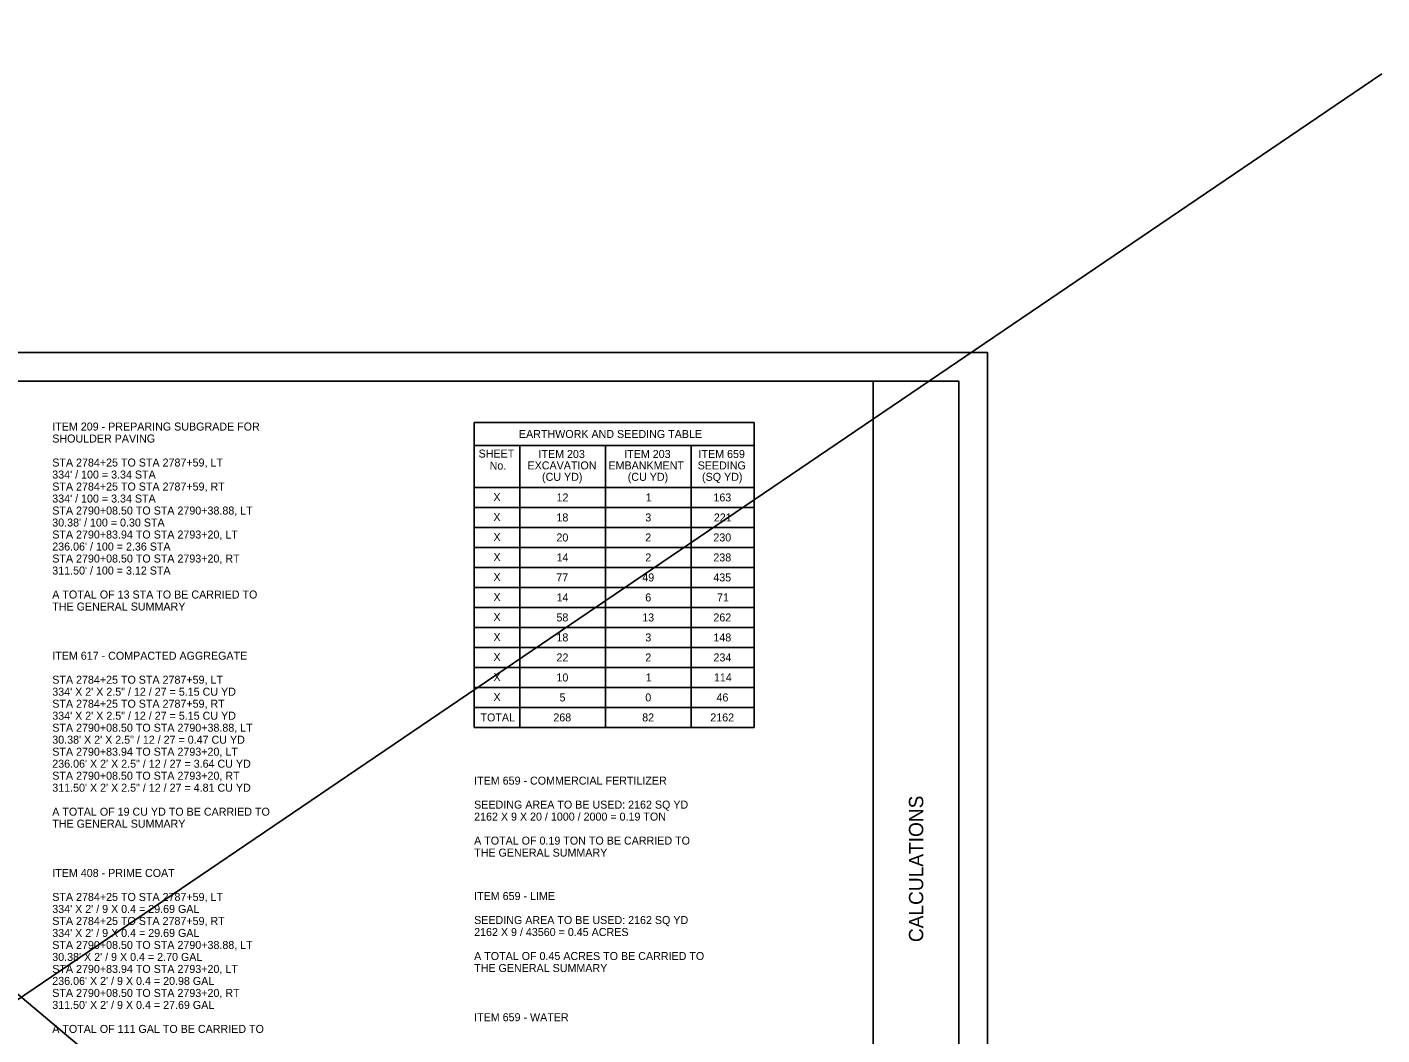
# Model space of a CAD drawing. Extents: x 0 to 126, y 0 to 48.
# Drawn here: x 101.92 to 125.62, y 30.04 to 47.67 of the extents above; entities that cross this region are included whole.
import ezdxf

# ---------------------------------------------------------------- set-up
doc = ezdxf.new("R2010")
doc.units = 0
for name, color, linetype in [('SH_Border', 7, 'Continuous'), ('SH_Cut_Line', 7, 'Continuous'), ('SH_Data', 7, 'Continuous'), ('SH_Text', 7, 'Continuous'), ('TX_P_1', 7, 'Continuous')]:
    doc.layers.add(name, color=color, linetype=linetype)

msp = doc.modelspace()

# ---------------------------------------------------------------- linework, layer by layer
at = {"layer": 'SH_Border'}
msp.add_line((116.721, 20.477), (116.721, 41.477), dxfattribs=at)
msp.add_lwpolyline([(86.221, 41.477), (118.221, 41.477), (118.221, 20.477), (86.221, 20.477)], close=True, dxfattribs=at)
at = {"layer": 'SH_Cut_Line'}
msp.add_lwpolyline([(84.721, 19.977), (118.721, 19.977), (118.721, 41.977), (84.721, 41.977)], close=True, dxfattribs=at)
at = {"layer": 'SH_Text'}
for p, q in [((81.554, 47.674), (123.873, 12.206)), ((125.622, 46.858), (82.136, 17.34))]:
    msp.add_line(p, q, dxfattribs=at)
at = {"layer": 'TX_P_1'}
for p, q in [((114.638, 40.753), (109.738, 40.753)), ((109.738, 40.753), (109.738, 35.417)), ((114.638, 40.753), (114.638, 35.417)), ((114.638, 40.353), (109.738, 40.353)), ((110.538, 40.353), (110.538, 35.417)), ((112.038, 40.353), (112.038, 35.417)), ((113.538, 40.353), (113.538, 35.417)), ((114.638, 39.617), (109.738, 39.617)), ((114.638, 39.267), (109.738, 39.267)), ((114.638, 38.917), (109.738, 38.917)), ((114.638, 38.567), (109.738, 38.567)), ((114.638, 38.217), (109.738, 38.217)), ((114.638, 37.867), (109.738, 37.867)), ((114.638, 37.517), (109.738, 37.517)), ((114.638, 37.167), (109.738, 37.167)), ((114.638, 36.817), (109.738, 36.817)), ((114.638, 36.467), (109.738, 36.467)), ((114.638, 36.117), (109.738, 36.117)), ((114.638, 35.767), (109.738, 35.767)), ((114.638, 35.417), (109.738, 35.417))]:
    msp.add_line(p, q, dxfattribs=at)

# ---------------------------------------------------------------- texts
at = {"layer": 'SH_Data'}
msp.add_text('CALCULATIONS', height=0.25, rotation=90, dxfattribs=at).set_placement((117.596, 31.66))
at = {"layer": 'TX_P_1'}
for s, p in [('SHOULDER PAVING', (102.356, 40.403)), ('ITEM 209 - PREPARING SUBGRADE FOR', (102.356, 40.613)), ('EARTHWORK AND SEEDING TABLE', (110.522, 40.483)), ('STA 2784+25 TO STA 2787+59, LT', (102.356, 39.983)), ('SHEET', (109.816, 40.14)), ('No.', (110.009, 39.93)), ('EXCAVATION', (110.672, 39.933)), ('ITEM 203', (110.864, 40.133)), ('EMBANKMENT', (112.088, 39.933)), ('ITEM 203', (112.364, 40.133)), ('SEEDING', (113.649, 39.933)), ('ITEM 659', (113.664, 40.133)), ("334' / 100 = 3.34 STA", (102.356, 39.773)), ('(CU YD)', (110.926, 39.733)), ('(CU YD)', (112.426, 39.733)), ('(SQ YD)', (113.726, 39.733)), ('STA 2784+25 TO STA 2787+59, RT', (102.356, 39.563)), ("334' / 100 = 3.34 STA", (102.356, 39.353)), ('X', (110.075, 39.379)), ('12', (111.179, 39.372)), ('1', (112.741, 39.372)), ('163', (113.925, 39.372)), ('STA 2790+08.50 TO STA 2790+38.88, LT', (102.356, 39.143)), ('X', (110.075, 39.029)), ('18', (111.178, 39.022)), ('3', (112.733, 39.022)), ('221', (113.932, 39.022)), ("30.38' / 100 = 0.30 STA", (102.356, 38.933)), ('STA 2790+83.94 TO STA 2793+20, LT', (102.356, 38.723)), ("236.06' / 100 = 2.36 STA", (102.356, 38.513)), ('X', (110.076, 38.679)), ('20', (111.178, 38.672)), ('2', (112.732, 38.672)), ('230', (113.924, 38.672)), ('STA 2790+08.50 TO STA 2793+20, RT', (102.356, 38.303)), ('X', (110.076, 38.329)), ('14', (111.18, 38.322)), ('2', (112.733, 38.322)), ('238', (113.924, 38.322)), ("311.50' / 100 = 3.12 STA", (102.356, 38.093)), ('X', (110.076, 37.979)), ('77', (111.175, 37.972)), ('49', (112.68, 37.972)), ('435', (113.923, 37.972)), ('A TOTAL OF 13 STA TO BE CARRIED TO', (102.356, 37.673)), ('X', (110.076, 37.629)), ('14', (111.18, 37.622)), ('6', (112.732, 37.622)), ('71', (113.987, 37.622)), ('THE GENERAL SUMMARY', (102.356, 37.463)), ('X', (110.076, 37.279)), ('58', (111.178, 37.272)), ('13', (112.679, 37.272)), ('262', (113.924, 37.272)), ('X', (110.076, 36.929)), ('18', (111.178, 36.922)), ('3', (112.733, 36.922)), ('148', (113.924, 36.922)), ('ITEM 617 - COMPACTED AGGREGATE', (102.356, 36.602)), ('X', (110.076, 36.579)), ('22', (111.179, 36.572)), ('2', (112.733, 36.572)), ('234', (113.926, 36.572)), ('STA 2784+25 TO STA 2787+59, LT', (102.356, 36.182)), ('X', (110.076, 36.229)), ('10', (111.178, 36.222)), ('1', (112.741, 36.222)), ('114', (113.933, 36.222)), ('334\' X 2\' X 2.5" / 12 / 27 = 5.15 CU YD', (102.356, 35.972)), ('STA 2784+25 TO STA 2787+59, RT', (102.356, 35.762)), ('X', (110.076, 35.879)), ('5', (111.232, 35.872)), ('0', (112.733, 35.872)), ('46', (113.978, 35.872)), ('334\' X 2\' X 2.5" / 12 / 27 = 5.15 CU YD', (102.356, 35.552)), ('TOTAL', (109.849, 35.522)), ('268', (111.124, 35.522)), ('82', (112.679, 35.522)), ('2162', (113.87, 35.522)), ('STA 2790+08.50 TO STA 2790+38.88, LT', (102.356, 35.342)), ('30.38\' X 2\' X 2.5" / 12 / 27 = 0.47 CU YD', (102.356, 35.132)), ('STA 2790+83.94 TO STA 2793+20, LT', (102.356, 34.922)), ('236.06\' X 2\' X 2.5" / 12 / 27 = 3.64 CU YD', (102.356, 34.712)), ('STA 2790+08.50 TO STA 2793+20, RT', (102.356, 34.502)), ('311.50\' X 2\' X 2.5" / 12 / 27 = 4.81 CU YD', (102.356, 34.292)), ('ITEM 659 - COMMERCIAL FERTILIZER', (109.738, 34.416)), ('SEEDING AREA TO BE USED: 2162 SQ YD', (109.738, 33.996)), ('A TOTAL OF 19 CU YD TO BE CARRIED TO', (102.356, 33.872)), ('2162 X 9 X 20 / 1000 / 2000 = 0.19 TON', (109.738, 33.786)), ('THE GENERAL SUMMARY', (102.356, 33.662)), ('A TOTAL OF 0.19 TON TO BE CARRIED TO', (109.738, 33.366)), ('THE GENERAL SUMMARY', (109.738, 33.156)), ('ITEM 408 - PRIME COAT', (102.356, 32.8)), ('STA 2784+25 TO STA 2787+59, LT', (102.356, 32.38)), ('ITEM 659 - LIME', (109.738, 32.396)), ("334' X 2' / 9 X 0.4 = 29.69 GAL", (102.356, 32.17)), ('STA 2784+25 TO STA 2787+59, RT', (102.356, 31.96)), ('SEEDING AREA TO BE USED: 2162 SQ YD', (109.738, 31.976)), ("334' X 2' / 9 X 0.4 = 29.69 GAL", (102.356, 31.75)), ('2162 X 9 / 43560 = 0.45 ACRES', (109.738, 31.766)), ('STA 2790+08.50 TO STA 2790+38.88, LT', (102.356, 31.54)), ("30.38' X 2' / 9 X 0.4 = 2.70 GAL", (102.356, 31.33)), ('A TOTAL OF 0.45 ACRES TO BE CARRIED TO', (109.738, 31.346)), ('STA 2790+83.94 TO STA 2793+20, LT', (102.356, 31.12)), ("236.06' X 2' / 9 X 0.4 = 20.98 GAL", (102.356, 30.91)), ('THE GENERAL SUMMARY', (109.738, 31.136)), ('STA 2790+08.50 TO STA 2793+20, RT', (102.356, 30.7)), ("311.50' X 2' / 9 X 0.4 = 27.69 GAL", (102.356, 30.49)), ('ITEM 659 - WATER', (109.738, 30.275)), ('A TOTAL OF 111 GAL TO BE CARRIED TO', (102.356, 30.07))]:
    msp.add_text(s, height=0.14, dxfattribs=at).set_placement(p)

doc.saveas('drawing.dxf')
